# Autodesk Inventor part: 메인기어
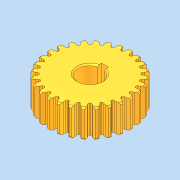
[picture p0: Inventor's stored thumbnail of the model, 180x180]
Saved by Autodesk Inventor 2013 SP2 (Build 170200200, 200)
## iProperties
Company: 한국ATC센터
Created: 2014-12
Part Number: 메인기어
Document SubType Name: Modeling
Designer: KYOUNG IL JANG
Density: 1 g/cm^3
Mass: 43.883 g
Surface Area: 122.661 cm^2
Volume: 43.883 cm^3
Material: 일반
Author: KYOUNG IL JANG
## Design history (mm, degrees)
sketch "스케치1"
  geometry: C1 r 25.5 at (0, 0); A1 r 1.064 centre (-2.94, 26.392) between (-2.696, 25.357) and (-1.877, 26.361); A2 r 6.991 centre (5.094, 25.835) between (-1.626, 27.763) and (-1.877, 26.361); A3 r 11.864 centre (9.774, 24.478) between (-0.731, 29.991) and (-1.626, 27.763); A4 r 1.064 centre (2.94, 26.392) between (1.877, 26.361) and (2.696, 25.357); A5 r 6.991 centre (-5.094, 25.835) between (1.877, 26.361) and (1.626, 27.763); A6 r 11.864 centre (-9.774, 24.478) between (1.626, 27.763) and (0.731, 29.991); A7 r 25.5 centre (0, 0) between (2.696, 25.357) and (-2.696, 25.357); A8 r 30 centre (0, 0) between (0.731, 29.991) and (-0.731, 29.991); 1 further point
  constraints: 16 point on circle, 9 centre point, 2 coincident, 1 concentric
extrude "돌출1" new body sketch "스케치1" stored distance "d0" = 20; taper "d1" = 0 deg
extrude "돌출2" join sketch "스케치1" stored distance "d2" = 20; taper "d3" = 0 deg
chamfer "모따기1" distance "d4" = 1; stored, may be unused: second distance "d5" = 2, angle "d6" = 45 deg
hole "구멍1" diameter "d12" = 17; stored, may be unused: countersink angle "d16" = 90 deg, drill point angle "d18" = 118 deg; dims "d10" = 10, "d11" = 10, "d13" = 6, "d14" = 4, "d15" = 2, "d17" = 8
sketch "스케치2"
  geometry: L1 (-2.5, 8.124)-(-2.5, 10.8); L2 (-2.5, 10.8)-(2.5, 10.8); L3 (2.5, 10.8)-(2.5, 8.124); A1 r 8.5 centre (0, 0) between (-2.5, 8.124) and (2.5, 8.124) reference; 1 further point
  constraints: 6 end point, 2 parallel, 2 point on circle, 1 perpendicular, 1 vertical
  dimensions: "d19" = 5 distance of L1.end L2.end; "d20" = 2.3 distance edge to line of A1 L2
extrude "돌출3" cut sketch "스케치2" stored distance "d21" = 20; taper "d22" = 0 deg
chamfer "모따기2" distance "d23" = 1; stored, may be unused: second distance "d24" = 2, angle "d25" = 45 deg
node "솔리드1"
pattern_circular "원형 패턴1" dims angle "d8" = 360 deg
